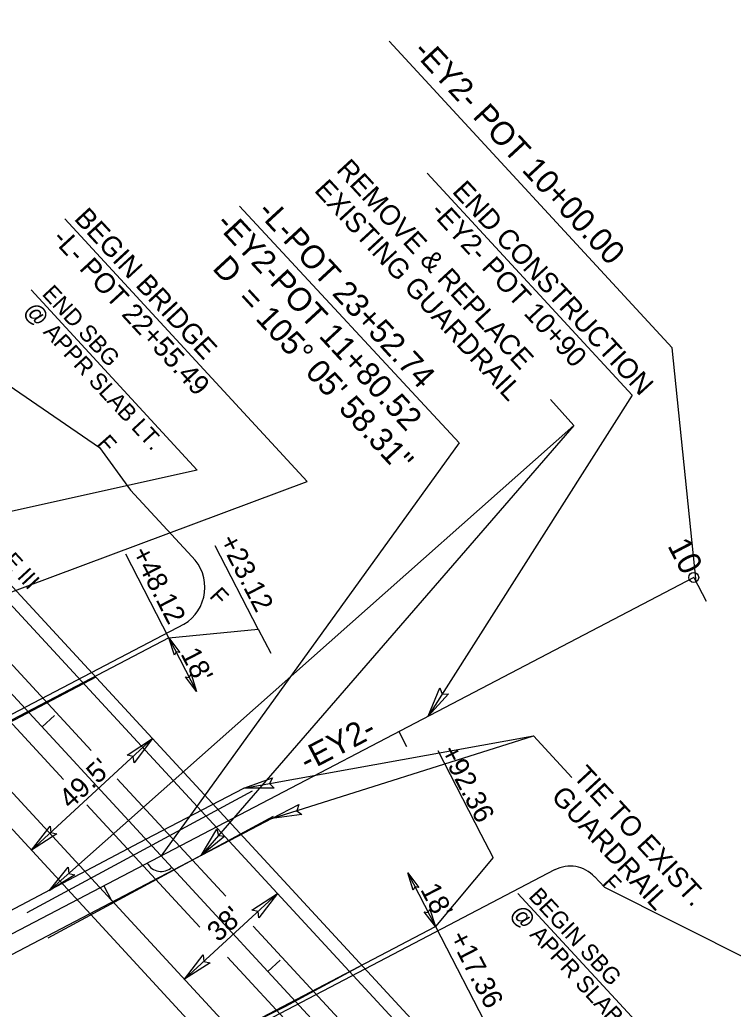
# Model space of a CAD drawing. Extents: x 1702862 to 1704514, y 793768 to 796215.
# Drawn here: x 1703529.1 to 1703743.4, y 794921.9 to 795219.2 of the extents above; entities that cross this region are included whole.
import ezdxf

# ---------------------------------------------------------------- set-up
doc = ezdxf.new("R2010")
doc.units = 0
for name, color, linetype in [('Exist Horizontal Alignment', 7, 'Continuous'), ('Exist Horizontal Alignment Direction Label', 7, 'Continuous'), ('Exist Horizontal Alignment Station Label', 7, 'Continuous'), ('Exist Horizontal Alignment Tick Label', 7, 'Continuous'), ('Exist Horizontal Alignment Tick Large', 7, 'Continuous'), ('Exist Horizontal Alignment Tick Small', 7, 'Continuous'), ('Old_Level_30', 7, 'Continuous'), ('Prop Dimension', 7, 'Continuous'), ('Prop Dimension Text', 7, 'Continuous'), ('Prop DSN Text', 7, 'Continuous'), ('Prop EOT', 7, 'Continuous'), ('Prop Guardrail', 7, 'Continuous'), ('Prop Guardrail Anchor Unit CELL', 7, 'Continuous'), ('Prop Horizontal Alignment', 7, 'Continuous'), ('Prop Horizontal Alignment Station Label', 7, 'Continuous'), ('Prop Horizontal Alignment Tick Small', 7, 'Continuous'), ('Prop Lane Lines', 7, 'Continuous'), ('Prop Leader Line Medium', 7, 'Continuous'), ('Prop Roadway Bridge', 7, 'Continuous'), ('Prop SS Fill Line', 7, 'Continuous'), ('Prop SS Misc', 7, 'Continuous'), ('Prop Terminator CELL', 7, 'Continuous')]:
    doc.layers.add(name, color=color, linetype=linetype)

msp = doc.modelspace()

# ---------------------------------------------------------------- linework, layer by layer
at = {"layer": 'Exist Horizontal Alignment'}
msp.add_line((1703731.56, 795051.6), (1703391.21, 794873.6), dxfattribs=at)
at = {"layer": 'Exist Horizontal Alignment Station Label'}
for p, q in [((1703595.08, 795163.16), (1703661.15, 795092.04)), ((1703661.15, 795092.04), (1703571.59, 794967.94))]:
    msp.add_line(p, q, dxfattribs=at)
msp.add_lwpolyline([(1703732.26, 795050.27), (1703725.12, 795120.64), (1703640.05, 795212.74)], dxfattribs=at)
msp.add_circle((1703731.56, 795051.6), 1.5, dxfattribs=at)
at = {"layer": 'Exist Horizontal Alignment Tick Large'}
msp.add_line((1703731.56, 795051.6), (1703735.27, 795044.51), dxfattribs=at)
at = {"layer": 'Exist Horizontal Alignment Tick Small'}
for p, q in [((1703642.95, 795005.26), (1703645.26, 795000.83)), ((1703554.34, 794958.91), (1703556.65, 794954.48))]:
    msp.add_line(p, q, dxfattribs=at)
at = {"layer": 'Old_Level_30'}
for p, q in [((1703531.3, 794950.91), (1703599.01, 794987.46)), ((1703537.6, 794943.27), (1703605.31, 794979.82))]:
    msp.add_line(p, q, dxfattribs=at)
at = {"layer": 'Prop Dimension'}
for p, q in [((1703532.64, 794969.6), (1703569.01, 795003.17)), ((1703578.62, 794930.85), (1703606.54, 794956.62))]:
    msp.add_line(p, q, dxfattribs=at)
msp.add_arc((1703571.59, 794967.94), 4.69, 207.6095, 312.7091, dxfattribs=at)
at = {"layer": 'Prop Dimension Text'}
for p, q in [((1703600.75, 795036.05), (1703587.8, 795061.13)), ((1703573.9, 795033.47), (1703560.94, 795058.55)), ((1703573.9, 795033.47), (1703582.22, 795017.35)), ((1703667.72, 794974.39), (1703654.76, 794999.47)), ((1703645.66, 794962.82), (1703653.98, 794946.7)), ((1703653.98, 794946.7), (1703671.12, 794913.52))]:
    msp.add_line(p, q, dxfattribs=at)
at = {"layer": 'Prop EOT'}
for p, q in [((1703259.9, 795332.15), (1703737.14, 794815.13)), ((1703418.98, 795103.79), (1703636.58, 794868.05)), ((1703573.9, 795033.47), (1703600.75, 795036.05)), ((1703600.71, 795036.03), (1703604.53, 795028.82)), ((1703573.9, 795033.47), (1703484.16, 794986.54)), ((1703671.33, 794967.48), (1703667.72, 794974.39)), ((1703671.33, 794967.48), (1703653.98, 794946.7)), ((1703564.25, 794899.77), (1703653.98, 794946.7))]:
    msp.add_line(p, q, dxfattribs=at)
for points in [[(1703551.93, 795021.68), (1703506.62, 794997.79)], [(1703586.27, 794911.5), (1703608.79, 794922.72), (1703631.89, 794935.05)]]:
    msp.add_lwpolyline(points, dxfattribs=at)
at = {"layer": 'Prop Guardrail'}
for p, q in [((1703566.95, 794972.97), (1703596.4, 794988.25)), ((1703604.81, 794979.13), (1703575.44, 794963.77)), ((1703492.38, 794933.6), (1703566.95, 794972.97)), ((1703575.44, 794963.77), (1703500.62, 794924.67))]:
    msp.add_line(p, q, dxfattribs=at)
at = {"layer": 'Prop Horizontal Alignment'}
msp.add_line((1703246.67, 795319.94), (1703723.92, 794802.92), dxfattribs=at)
at = {"layer": 'Prop Horizontal Alignment Tick Small'}
for p, q in [((1703535.82, 795006.69), (1703539.5, 795010.08)), ((1703603.65, 794933.21), (1703607.32, 794936.6))]:
    msp.add_line(p, q, dxfattribs=at)
at = {"layer": 'Prop Lane Lines'}
for p, q in [((1703347.89, 795219.14), (1703550.56, 794999.58)), ((1703339.07, 795211), (1703542.22, 794990.92)), ((1703558.4, 794991.09), (1703590.98, 794955.79)), ((1703549.28, 794983.27), (1703583.2, 794946.52)), ((1703599.26, 794946.81), (1703728.33, 794806.99)), ((1703591.49, 794937.54), (1703719.51, 794798.85))]:
    msp.add_line(p, q, dxfattribs=at)
at = {"layer": 'Prop Leader Line Medium'}
for p, q in [((1703542.61, 795159.41), (1703615.49, 795080.46)), ((1703532.59, 795138.03), (1703582.45, 795083.79)), ((1703695.56, 795097.27), (1703537.91, 794957.38)), ((1703582.45, 795083.79), (1703509.44, 795067.71)), ((1703505.63, 795039.4), (1703615.49, 795080.46)), ((1703596.4, 794988.25), (1703683.43, 795003.97)), ((1703604.81, 794979.13), (1703683.43, 795003.97)), ((1703683.43, 795003.97), (1703694.94, 794991.5))]:
    msp.add_line(p, q, dxfattribs=at)
for points in [[(1703651.52, 795173.12), (1703713.12, 795106.39), (1703651.81, 795009.89)], [(1703688.5, 795105.09), (1703695.56, 795097.27), (1703583.62, 794968.06)], [(1703675.15, 794888.19), (1703722.72, 794909.06), (1703678.78, 794956.66)]]:
    msp.add_lwpolyline(points, dxfattribs=at)
at = {"layer": 'Prop Roadway Bridge'}
for p, q in [((1703525.81, 795049.97), (1703658.78, 794905.92)), ((1703480.41, 795026.18), (1703613.32, 794882.19))]:
    msp.add_line(p, q, dxfattribs=at)
at = {"layer": 'Prop SS Fill Line'}
for p, q in [((1703510.78, 795119.67), (1703553.07, 795090.66)), ((1703553.07, 795090.66), (1703562.41, 795077.87)), ((1703562.41, 795077.87), (1703580.79, 795057.85)), ((1703578.45, 795037.54), (1703491.11, 794991.87)), ((1703689.78, 794963.74), (1703573.15, 794902.74)), ((1703704.77, 794958.5), (1703701.8, 794961.69)), ((1703704.77, 794958.5), (1703749.05, 794936.28))]:
    msp.add_line(p, q, dxfattribs=at)
for centre, radius, start, end in [((1703571.82, 795048.6), 12.89, 300.952, 45.9027), ((1703694.44, 794954.84), 10, 42.932, 117.6095)]:
    msp.add_arc(centre, radius, start, end, dxfattribs=at)
at = {"layer": 'Prop Terminator CELL'}
for points in [[(1703575.55, 795028.24), (1703573.9, 795033.47), (1703577.24, 795029.08), (1703576.07, 795029.26)], [(1703580.57, 795022.58), (1703582.22, 795017.35), (1703578.87, 795021.73), (1703580.04, 795021.56)], [(1703657.95, 795016.65), (1703651.81, 795009.89), (1703655.32, 795018.38), (1703656.05, 795016.56)], [(1703561.35, 794998.21), (1703569.01, 795003.17), (1703563.45, 794995.86), (1703563.21, 794997.81)], [(1703605.53, 794988.32), (1703596.4, 794988.25), (1703605.02, 794991.43), (1703604.17, 794989.65)], [(1703613.86, 794980.37), (1703604.81, 794979.13), (1703612.96, 794983.39), (1703612.34, 794981.51)], [(1703540.3, 794974.56), (1703532.64, 794969.6), (1703538.2, 794976.91), (1703538.44, 794974.96)], [(1703590.68, 794973.84), (1703583.62, 794968.06), (1703588.33, 794975.94), (1703588.79, 794974.03)], [(1703545.67, 794962.2), (1703537.91, 794957.38), (1703543.61, 794964.59), (1703543.82, 794962.63)], [(1703647.31, 794957.6), (1703645.66, 794962.82), (1703649, 794958.44), (1703647.84, 794958.61)], [(1703598.87, 794951.66), (1703606.54, 794956.62), (1703600.97, 794949.31), (1703600.73, 794951.26)], [(1703652.33, 794951.93), (1703653.98, 794946.7), (1703650.64, 794951.09), (1703651.81, 794950.92)], [(1703586.28, 794935.81), (1703578.62, 794930.85), (1703584.18, 794938.16), (1703584.42, 794936.21)]]:
    msp.add_lwpolyline(points, close=True, dxfattribs=at)

# ---------------------------------------------------------------- texts
at = {"layer": 'Exist Horizontal Alignment Direction Label'}
msp.add_text('-EY2-', height=7, rotation=27.6095, dxfattribs=at).set_placement((1703615.47, 794993.07))
at = {"layer": 'Exist Horizontal Alignment Station Label'}
msp.add_text('-EY2- POT 10+00.00', height=7, rotation=312.7091, dxfattribs=at).set_placement((1703646.87, 795209.44))
at = {"layer": 'Exist Horizontal Alignment Tick Label'}
msp.add_text('10', height=7, rotation=297.6095, dxfattribs=at).set_placement((1703723.55, 795061.16))
at = {"layer": 'Prop Dimension Text'}
for s, rotation, p in [('REMOVE & REPLACE ', 312.7091, (1703623.93, 795173.87)), ('EXISTING GUARDRAIL', 312.7091, (1703617.32, 795167.76)), ('+23.12', 297.3125, (1703588.91, 795062.68)), ('+48.12', 297.3125, (1703562.56, 795059.04)), ("18'", 297.3125, (1703577.31, 795028.64)), ('+92.36', 297.3125, (1703655.32, 794999.34)), ("49.5'", 42.7091, (1703544.33, 794981.76)), ('TIE TO EXIST.', 312.7091, (1703695.07, 794991.61)), ('GUARDRAIL', 312.7091, (1703688.46, 794985.51)), ("18'", 297.3125, (1703649.33, 794957.86)), ("38'", 42.7091, (1703588.79, 794941.8)), ('+17.36', 297.3125, (1703658, 794943.56))]:
    msp.add_text(s, height=6, rotation=rotation, dxfattribs=at).set_placement(p)
at = {"layer": 'Prop DSN Text'}
for s, height, p in [('END CONSTRUCTION', 6, (1703658.75, 795167.4)), ('BEGIN BRIDGE', 6, (1703545.18, 795159.23)), ('-EY2- POT 10+90', 6, (1703652.14, 795161.29)), ('-L- POT 22+55.49', 6, (1703538.57, 795153.12)), ('END SBG', 5, (1703535.55, 795136.61)), ('@ APPR SLAB LT.', 5, (1703530.04, 795131.53)), ('BEGIN SBG', 5, (1703681.71, 794955.54)), ('@ APPR SLAB LT.', 5, (1703676.2, 794950.45))]:
    msp.add_text(s, height=height, rotation=312.7091, dxfattribs=at).set_placement(p)
at = {"layer": 'Prop Guardrail Anchor Unit CELL'}
msp.add_text('TYPE III', height=5, rotation=312.7301, dxfattribs=at).set_placement((1703514.95, 795065.82))
at = {"layer": 'Prop Horizontal Alignment Station Label'}
for s, p in [('-L-POT 23+52.74', (1703600.11, 795161.23)), ('-EY2-POT 11+80.52', (1703587.65, 795157.65)), ('D', (1703586.7, 795144.32)), ('= 105%%d 05\' 58.31"', (1703594.21, 795135.14))]:
    msp.add_text(s, height=7, rotation=312.7091, dxfattribs=at).set_placement(p)
at = {"layer": 'Prop SS Misc'}
for rotation, p in [(311.4091, (1703552.13, 795091.72)), (312.7091, (1703585.84, 795045.79)), (312.7091, (1703703.8, 794959.54))]:
    msp.add_text('F', height=5, rotation=rotation, dxfattribs=at).set_placement(p)

doc.saveas('drawing.dxf')
